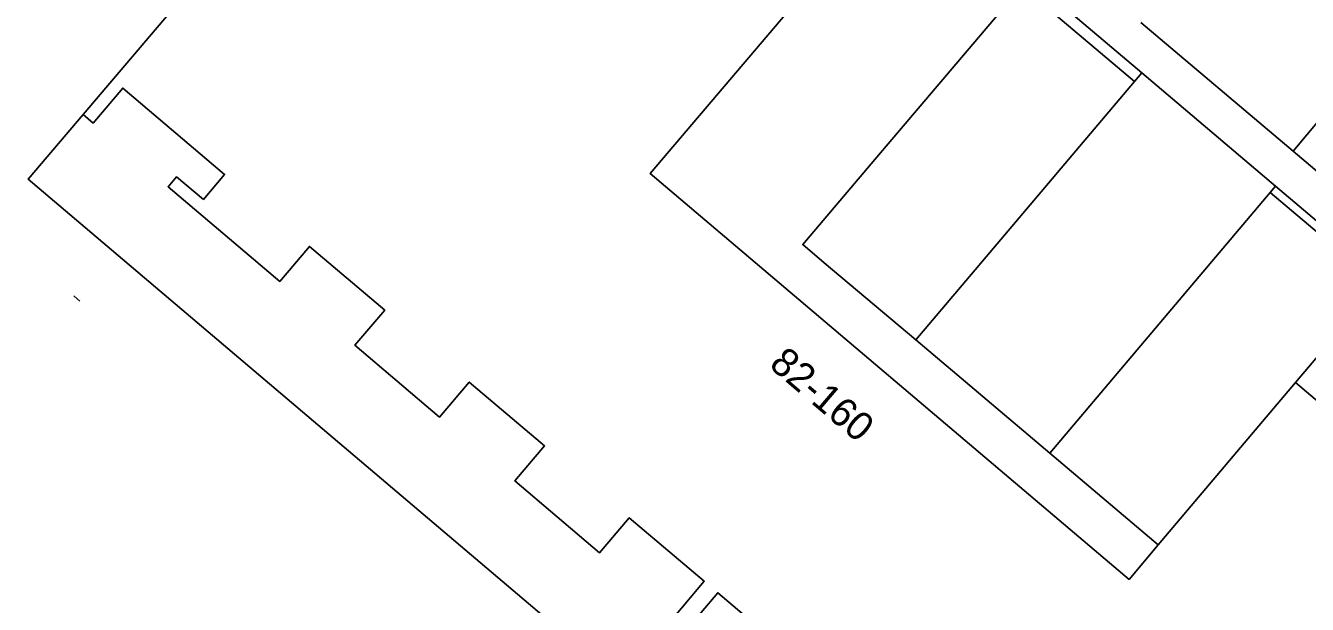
# Model space of a CAD drawing. Extents: x 156414 to 157775, y 382335 to 383765.
# Drawn here: x 156837.13 to 156882.05, y 382367.08 to 382387.38 of the extents above; entities that cross this region are included whole.
import ezdxf

# ---------------------------------------------------------------- set-up
doc = ezdxf.new("R2010")
doc.units = 0
for name, color, linetype in [('IMGEO_Erf', 7, 'Continuous'), ('IMGEO_Grasland_overig', 7, 'Continuous'), ('IMGEO_Pand', 7, 'Continuous'), ('IMGEO_Pand_nummerreeks', 7, 'Continuous'), ('IMGEO_Parkeervlak_open', 7, 'Continuous'), ('IMGEO_Rijbaan_lokaal_gesloten', 7, 'Continuous'), ('IMGEO_Rijbaan_lokaal_open', 7, 'Continuous'), ('IMGEO_Voetpad_open', 7, 'Continuous')]:
    doc.layers.add(name, color=color, linetype=linetype)

msp = doc.modelspace()

# ---------------------------------------------------------------- linework, layer by layer
at = {"layer": 'IMGEO_Erf'}
msp.add_lwpolyline([(156881.054, 382348.684), (156879.132, 382346.42), (156837.223, 382381.992), (156839.145, 382384.257)], dxfattribs=at)
at = {"layer": 'IMGEO_Grasland_overig'}
msp.add_lwpolyline([(156838.828, 382377.89), (156838.818, 382377.898)], dxfattribs=at)
at = {"layer": 'IMGEO_Pand'}
for points in [[(156839.145, 382384.257), (156849.716, 382396.712), (156852.667, 382394.197), (156855.263, 382397.254), (156864.877, 382389.09), (156859.023, 382382.186), (156875.803, 382367.957), (156876.827, 382369.169)], [(156839.145, 382384.257), (156839.496, 382383.959), (156840.538, 382385.186), (156844.106, 382382.158), (156843.361, 382381.281), (156842.424, 382382.077), (156842.126, 382381.726), (156846.037, 382378.407), (156847.079, 382379.634), (156849.717, 382377.395), (156848.675, 382376.168), (156851.641, 382373.65), (156852.682, 382374.878), (156855.32, 382372.639), (156854.278, 382371.411), (156857.244, 382368.894), (156858.286, 382370.121), (156860.916, 382367.889), (156859.874, 382366.661)], [(156876.827, 382369.169), (156881.639, 382374.864)], [(156881.639, 382374.864), (156894.216, 382364.192), (156881.054, 382348.684)], [(156860.347, 382366.26), (156861.389, 382367.488), (156864.012, 382365.262)]]:
    msp.add_lwpolyline(points, dxfattribs=at)
at = {"layer": 'IMGEO_Parkeervlak_open'}
for points in [[(156868.324, 382376.353), (156865.122, 382379.058), (156864.368, 382379.696), (156866.766, 382382.53), (156872.041, 382388.764), (156875.993, 382385.42)], [(156880.749, 382381.527), (156884.553, 382378.309), (156881.639, 382374.864)], [(156876.827, 382369.169), (156873.023, 382372.383)]]:
    msp.add_lwpolyline(points, dxfattribs=at)
at = {"layer": 'IMGEO_Rijbaan_lokaal_gesloten'}
for points in [[(156838.828, 382377.89), (156838.828, 382377.89)], [(156839.033, 382377.716), (156838.828, 382377.89)]]:
    msp.add_lwpolyline(points, dxfattribs=at)
at = {"layer": 'IMGEO_Rijbaan_lokaal_open'}
for points in [[(156881.551, 382382.97), (156876.211, 382387.486)], [(156884.481, 382386.477), (156881.551, 382382.97)], [(156875.993, 382385.42), (156876.247, 382385.72)], [(156880.938, 382381.751), (156876.247, 382385.72)], [(156875.993, 382385.42), (156870.535, 382378.969), (156868.324, 382376.353)], [(156880.938, 382381.751), (156880.749, 382381.527)], [(156873.023, 382372.383), (156880.749, 382381.527)], [(156873.023, 382372.383), (156868.324, 382376.353)]]:
    msp.add_lwpolyline(points, dxfattribs=at)
at = {"layer": 'IMGEO_Voetpad_open'}
for points in [[(156876.247, 382385.72), (156849.783, 382408.111), (156821.763, 382431.828), (156791.675, 382457.364)], [(156884.303, 382380.643), (156881.551, 382382.97)], [(156899.797, 382365.794), (156880.938, 382381.751)]]:
    msp.add_lwpolyline(points, dxfattribs=at)

# ---------------------------------------------------------------- texts
at = {"layer": 'IMGEO_Pand_nummerreeks'}
msp.add_text('82-160', height=1, rotation=319.5033, dxfattribs=at).set_placement((156863.147, 382375.424))

doc.saveas('drawing.dxf')
